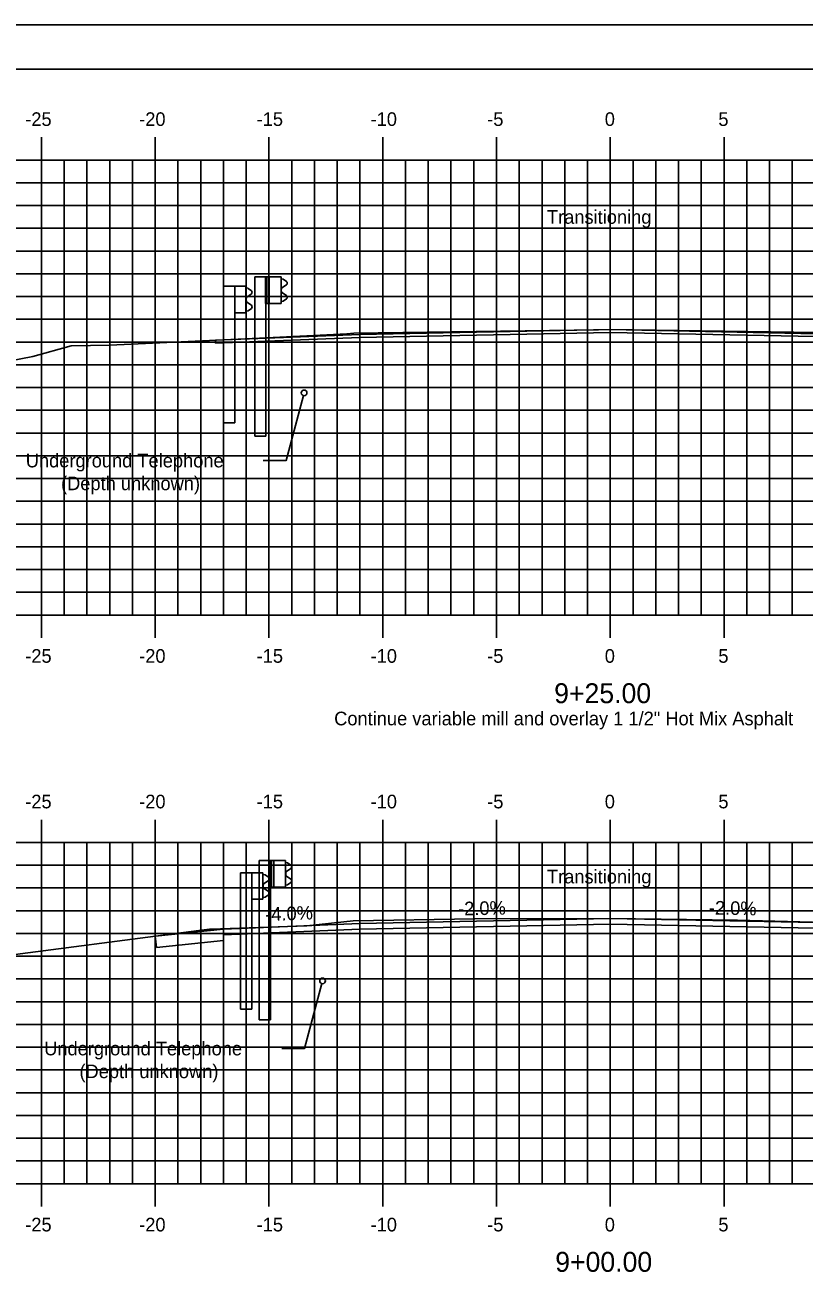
# Model space of a CAD drawing. Extents: x 2194502 to 2194968, y 863888 to 863998.
# Drawn here: x 2194672.8 to 2194707, y 863943.5 to 863998.4 of the extents above; entities that cross this region are included whole.
import ezdxf

# ---------------------------------------------------------------- set-up
doc = ezdxf.new("R2010")
doc.units = 0
for name, color, linetype in [('ANNOTATION', 7, 'Continuous'), ('BORDER', 7, 'Continuous'), ('D_Guardrail_Beam_Lt', 7, 'Continuous'), ('H_V ANNOTATION', 7, 'Continuous'), ('MAJOR', 7, 'Continuous'), ('MINOR', 7, 'Continuous'), ('PLOT BOUNDARY', 7, 'Continuous'), ('S_Guardrail_Beam', 7, 'Continuous'), ('S_Roadway_Centerline', 7, 'Continuous'), ('S_Utilities_Pole_Power', 7, 'Continuous'), ('TEMPLATE', 7, 'Continuous')]:
    doc.layers.add(name, color=color, linetype=linetype)

msp = doc.modelspace()

# ---------------------------------------------------------------- linework, layer by layer
at = {"layer": 'ANNOTATION'}
for points in [[(2194683.247, 863979.236), (2194684.247, 863979.236), (2194685.012, 863982.09)], [(2194684.057, 863953.387), (2194685.057, 863953.387), (2194685.822, 863956.241)]]:
    msp.add_lwpolyline(points, dxfattribs=at)
at = {"layer": 'BORDER'}
msp.add_lwpolyline([(2194623.499, 863891.446), (2194783.499, 863891.446), (2194783.499, 863996.446), (2194623.499, 863996.446)], close=True, dxfattribs=at)
at = {"layer": 'D_Guardrail_Beam_Lt'}
for p, q in [((2194682.871, 863987.31), (2194682.871, 863980.31)), ((2194683.342, 863987.31), (2194682.871, 863987.31)), ((2194684.029, 863987.31), (2194683.342, 863987.31)), ((2194683.342, 863987.31), (2194683.342, 863986.144)), ((2194683.404, 863987.31), (2194683.404, 863986.144)), ((2194683.509, 863987.31), (2194683.509, 863986.144)), ((2194684.029, 863986.144), (2194684.029, 863987.31)), ((2194684.029, 863987.227), (2194684.104, 863987.212)), ((2194684.263, 863986.962), (2194684.068, 863986.826)), ((2194684.119, 863987.206), (2194684.263, 863987.106)), ((2194684.034, 863986.762), (2194684.034, 863986.692)), ((2194684.068, 863986.627), (2194684.263, 863986.491)), ((2194683.342, 863986.144), (2194684.029, 863986.144)), ((2194683.363, 863980.31), (2194683.363, 863986.144)), ((2194684.104, 863986.241), (2194684.029, 863986.227)), ((2194684.263, 863986.348), (2194684.119, 863986.248)), ((2194683.363, 863980.31), (2194682.871, 863980.31)), ((2194683.07, 863961.652), (2194683.07, 863954.652)), ((2194683.541, 863961.652), (2194683.07, 863961.652)), ((2194684.228, 863961.652), (2194683.541, 863961.652)), ((2194683.541, 863961.652), (2194683.541, 863960.486)), ((2194683.603, 863961.652), (2194683.603, 863960.486)), ((2194683.708, 863961.652), (2194683.708, 863960.486)), ((2194684.228, 863960.486), (2194684.228, 863961.652)), ((2194684.228, 863961.569), (2194684.303, 863961.555)), ((2194684.462, 863961.305), (2194684.267, 863961.169)), ((2194684.318, 863961.548), (2194684.462, 863961.448)), ((2194684.233, 863961.104), (2194684.233, 863961.034)), ((2194684.267, 863960.97), (2194684.462, 863960.833)), ((2194684.462, 863960.69), (2194684.318, 863960.59)), ((2194683.541, 863960.486), (2194684.228, 863960.486)), ((2194683.562, 863954.652), (2194683.562, 863960.486)), ((2194684.303, 863960.584), (2194684.228, 863960.569)), ((2194683.562, 863954.652), (2194683.07, 863954.652))]:
    msp.add_line(p, q, dxfattribs=at)
for centre, major_axis, start_param, end_param in [((2194684.096, 863987.172), (0.0417, 0), 0.959931, 1.376053), ((2194684.213, 863987.034), (0.0877, 0), 5.323254, 7.243116), ((2194684.113, 863986.762), (-0.0789, 0), 5.323254, 6.283185), ((2194684.113, 863986.692), (-0.0789, 0), 6.283185, 7.243116), ((2194684.213, 863986.42), (0.0877, 0), 5.323254, 7.243116), ((2194684.096, 863986.282), (0.0417, 0), 4.907132, 5.323254), ((2194684.312, 863961.104), (-0.0789, 0), 5.323254, 6.283185), ((2194684.295, 863961.514), (0.0417, 0), 0.959931, 1.376053), ((2194684.412, 863961.376), (0.0877, 0), 5.323254, 7.243116), ((2194684.312, 863961.034), (-0.0789, 0), 6.283185, 7.243116), ((2194684.412, 863960.762), (0.0877, 0), 5.323254, 7.243116), ((2194684.295, 863960.624), (0.0417, 0), 4.907132, 5.323254)]:
    msp.add_ellipse(centre, major_axis=major_axis, ratio=0.995501, start_param=start_param, end_param=end_param, dxfattribs=at)
at = {"layer": 'MAJOR'}
for p, q in [((2194673.499, 863993.448), (2194673.499, 863992.446)), ((2194678.499, 863993.448), (2194678.499, 863992.446)), ((2194683.499, 863993.448), (2194683.499, 863992.446)), ((2194688.499, 863993.448), (2194688.499, 863992.446)), ((2194693.499, 863993.448), (2194693.499, 863992.446)), ((2194698.499, 863993.448), (2194698.499, 863992.446)), ((2194703.499, 863993.448), (2194703.499, 863992.446)), ((2194628.499, 863992.446), (2194768.499, 863992.446)), ((2194628.499, 863992.446), (2194768.499, 863992.446)), ((2194673.499, 863972.446), (2194673.499, 863992.446)), ((2194678.499, 863972.446), (2194678.499, 863992.446)), ((2194683.499, 863972.446), (2194683.499, 863992.446)), ((2194688.499, 863972.446), (2194688.499, 863992.446)), ((2194693.499, 863972.446), (2194693.499, 863992.446)), ((2194698.499, 863972.446), (2194698.499, 863992.446)), ((2194703.499, 863972.446), (2194703.499, 863992.446)), ((2194628.499, 863987.446), (2194768.499, 863987.446)), ((2194628.499, 863982.446), (2194768.499, 863982.446)), ((2194628.499, 863977.446), (2194768.499, 863977.446)), ((2194628.499, 863972.446), (2194768.499, 863972.446)), ((2194673.499, 863971.444), (2194673.499, 863972.446)), ((2194678.499, 863971.444), (2194678.499, 863972.446)), ((2194683.499, 863971.444), (2194683.499, 863972.446)), ((2194688.499, 863971.444), (2194688.499, 863972.446)), ((2194693.499, 863971.444), (2194693.499, 863972.446)), ((2194698.499, 863971.444), (2194698.499, 863972.446)), ((2194703.499, 863971.444), (2194703.499, 863972.446)), ((2194673.499, 863963.448), (2194673.499, 863962.446)), ((2194678.499, 863963.448), (2194678.499, 863962.446)), ((2194683.499, 863963.448), (2194683.499, 863962.446)), ((2194688.499, 863963.448), (2194688.499, 863962.446)), ((2194693.499, 863963.448), (2194693.499, 863962.446)), ((2194698.499, 863963.448), (2194698.499, 863962.446)), ((2194703.499, 863963.448), (2194703.499, 863962.446)), ((2194628.499, 863962.446), (2194768.499, 863962.446)), ((2194673.499, 863947.446), (2194673.499, 863962.446)), ((2194678.499, 863947.446), (2194678.499, 863962.446)), ((2194683.499, 863947.446), (2194683.499, 863962.446)), ((2194688.499, 863947.446), (2194688.499, 863962.446)), ((2194693.499, 863947.446), (2194693.499, 863962.446)), ((2194698.499, 863947.446), (2194698.499, 863962.446)), ((2194703.499, 863947.446), (2194703.499, 863962.446)), ((2194628.499, 863957.446), (2194768.499, 863957.446)), ((2194628.499, 863952.446), (2194768.499, 863952.446)), ((2194628.499, 863947.446), (2194768.499, 863947.446)), ((2194673.499, 863946.444), (2194673.499, 863947.446)), ((2194678.499, 863946.444), (2194678.499, 863947.446)), ((2194683.499, 863946.444), (2194683.499, 863947.446)), ((2194688.499, 863946.444), (2194688.499, 863947.446)), ((2194693.499, 863946.444), (2194693.499, 863947.446)), ((2194698.499, 863946.444), (2194698.499, 863947.446)), ((2194703.499, 863946.444), (2194703.499, 863947.446))]:
    msp.add_line(p, q, dxfattribs=at)
at = {"layer": 'MINOR'}
for p, q in [((2194674.499, 863972.446), (2194674.499, 863992.446)), ((2194675.499, 863972.446), (2194675.499, 863992.446)), ((2194676.499, 863972.446), (2194676.499, 863992.446)), ((2194677.499, 863972.446), (2194677.499, 863992.446)), ((2194679.499, 863972.446), (2194679.499, 863992.446)), ((2194680.499, 863972.446), (2194680.499, 863992.446)), ((2194681.499, 863972.446), (2194681.499, 863992.446)), ((2194682.499, 863972.446), (2194682.499, 863992.446)), ((2194684.499, 863972.446), (2194684.499, 863992.446)), ((2194685.499, 863972.446), (2194685.499, 863992.446)), ((2194686.499, 863972.446), (2194686.499, 863992.446)), ((2194687.499, 863972.446), (2194687.499, 863992.446)), ((2194689.499, 863972.446), (2194689.499, 863992.446)), ((2194690.499, 863972.446), (2194690.499, 863992.446)), ((2194691.499, 863972.446), (2194691.499, 863992.446)), ((2194692.499, 863972.446), (2194692.499, 863992.446)), ((2194694.499, 863972.446), (2194694.499, 863992.446)), ((2194695.499, 863972.446), (2194695.499, 863992.446)), ((2194696.499, 863972.446), (2194696.499, 863992.446)), ((2194697.499, 863972.446), (2194697.499, 863992.446)), ((2194699.499, 863972.446), (2194699.499, 863992.446)), ((2194700.499, 863972.446), (2194700.499, 863992.446)), ((2194701.499, 863972.446), (2194701.499, 863992.446)), ((2194702.499, 863972.446), (2194702.499, 863992.446)), ((2194704.499, 863972.446), (2194704.499, 863992.446)), ((2194705.499, 863972.446), (2194705.499, 863992.446)), ((2194706.499, 863972.446), (2194706.499, 863992.446)), ((2194628.499, 863991.446), (2194768.499, 863991.446)), ((2194628.499, 863990.446), (2194768.499, 863990.446)), ((2194628.499, 863989.446), (2194768.499, 863989.446)), ((2194628.499, 863988.446), (2194768.499, 863988.446)), ((2194628.499, 863986.446), (2194768.499, 863986.446)), ((2194628.499, 863985.446), (2194768.499, 863985.446)), ((2194628.499, 863984.446), (2194768.499, 863984.446)), ((2194628.499, 863983.446), (2194768.499, 863983.446)), ((2194628.499, 863981.446), (2194768.499, 863981.446)), ((2194628.499, 863980.446), (2194768.499, 863980.446)), ((2194628.499, 863979.446), (2194768.499, 863979.446)), ((2194628.499, 863978.446), (2194768.499, 863978.446)), ((2194628.499, 863976.446), (2194768.499, 863976.446)), ((2194628.499, 863975.446), (2194768.499, 863975.446)), ((2194628.499, 863974.446), (2194768.499, 863974.446)), ((2194628.499, 863973.446), (2194768.499, 863973.446)), ((2194674.499, 863947.446), (2194674.499, 863962.446)), ((2194675.499, 863947.446), (2194675.499, 863962.446)), ((2194676.499, 863947.446), (2194676.499, 863962.446)), ((2194677.499, 863947.446), (2194677.499, 863962.446)), ((2194679.499, 863947.446), (2194679.499, 863962.446)), ((2194680.499, 863947.446), (2194680.499, 863962.446)), ((2194681.499, 863947.446), (2194681.499, 863962.446)), ((2194682.499, 863947.446), (2194682.499, 863962.446)), ((2194684.499, 863947.446), (2194684.499, 863962.446)), ((2194685.499, 863947.446), (2194685.499, 863962.446)), ((2194686.499, 863947.446), (2194686.499, 863962.446)), ((2194687.499, 863947.446), (2194687.499, 863962.446)), ((2194689.499, 863947.446), (2194689.499, 863962.446)), ((2194690.499, 863947.446), (2194690.499, 863962.446)), ((2194691.499, 863947.446), (2194691.499, 863962.446)), ((2194692.499, 863947.446), (2194692.499, 863962.446)), ((2194694.499, 863947.446), (2194694.499, 863962.446)), ((2194695.499, 863947.446), (2194695.499, 863962.446)), ((2194696.499, 863947.446), (2194696.499, 863962.446)), ((2194697.499, 863947.446), (2194697.499, 863962.446)), ((2194699.499, 863947.446), (2194699.499, 863962.446)), ((2194700.499, 863947.446), (2194700.499, 863962.446)), ((2194701.499, 863947.446), (2194701.499, 863962.446)), ((2194702.499, 863947.446), (2194702.499, 863962.446)), ((2194704.499, 863947.446), (2194704.499, 863962.446)), ((2194705.499, 863947.446), (2194705.499, 863962.446)), ((2194706.499, 863947.446), (2194706.499, 863962.446)), ((2194628.499, 863961.446), (2194768.499, 863961.446)), ((2194628.499, 863960.446), (2194768.499, 863960.446)), ((2194628.499, 863959.446), (2194768.499, 863959.446)), ((2194628.499, 863958.446), (2194768.499, 863958.446)), ((2194628.499, 863956.446), (2194768.499, 863956.446)), ((2194628.499, 863955.446), (2194768.499, 863955.446)), ((2194628.499, 863954.446), (2194768.499, 863954.446)), ((2194628.499, 863953.446), (2194768.499, 863953.446)), ((2194628.499, 863951.446), (2194768.499, 863951.446)), ((2194628.499, 863950.446), (2194768.499, 863950.446)), ((2194628.499, 863949.446), (2194768.499, 863949.446)), ((2194628.499, 863948.446), (2194768.499, 863948.446))]:
    msp.add_line(p, q, dxfattribs=at)
at = {"layer": 'PLOT BOUNDARY'}
msp.add_lwpolyline([(2194615.406, 863888.387), (2194785.406, 863888.387), (2194785.406, 863998.387), (2194615.406, 863998.387)], close=True, dxfattribs=at)
at = {"layer": 'S_Guardrail_Beam'}
for p, q in [((2194681.5, 863986.898), (2194681.5, 863980.898)), ((2194681.992, 863986.898), (2194681.5, 863986.898)), ((2194682.482, 863986.898), (2194681.992, 863986.898)), ((2194681.992, 863986.898), (2194681.992, 863985.731)), ((2194682.482, 863985.731), (2194682.482, 863986.898)), ((2194682.482, 863986.825), (2194682.564, 863986.81)), ((2194682.724, 863986.56), (2194682.528, 863986.424)), ((2194682.58, 863986.803), (2194682.724, 863986.703)), ((2194682.495, 863986.36), (2194682.495, 863986.269)), ((2194682.528, 863986.204), (2194682.724, 863986.068)), ((2194682.724, 863985.925), (2194682.58, 863985.825)), ((2194681.992, 863980.898), (2194681.992, 863985.731)), ((2194681.992, 863985.731), (2194682.482, 863985.731)), ((2194682.564, 863985.818), (2194682.482, 863985.804)), ((2194681.992, 863980.898), (2194681.5, 863980.898)), ((2194682.253, 863961.116), (2194682.253, 863955.116)), ((2194682.745, 863961.116), (2194682.253, 863961.116)), ((2194683.234, 863961.116), (2194682.745, 863961.116)), ((2194682.745, 863961.116), (2194682.745, 863959.949)), ((2194683.234, 863959.949), (2194683.234, 863961.116)), ((2194683.234, 863961.043), (2194683.316, 863961.029)), ((2194683.477, 863960.779), (2194683.281, 863960.642)), ((2194683.333, 863961.022), (2194683.477, 863960.922)), ((2194683.248, 863960.578), (2194683.248, 863960.487)), ((2194683.281, 863960.423), (2194683.477, 863960.286)), ((2194683.477, 863960.143), (2194683.333, 863960.043)), ((2194682.745, 863955.116), (2194682.745, 863959.949)), ((2194682.745, 863959.949), (2194683.234, 863959.949)), ((2194683.316, 863960.037), (2194683.234, 863960.022)), ((2194682.745, 863955.116), (2194682.253, 863955.116))]:
    msp.add_line(p, q, dxfattribs=at)
for centre, major_axis, start_param, end_param in [((2194682.574, 863986.36), (-0.0789, 0), 5.323254, 6.283185), ((2194682.556, 863986.77), (0.0417, 0), 0.959931, 1.396263), ((2194682.673, 863986.632), (0.0877, 0), 5.323254, 7.243116), ((2194682.574, 863986.269), (-0.0789, 0), 6.283185, 7.243116), ((2194682.673, 863985.997), (0.0877, 0), 5.323254, 7.243116), ((2194682.556, 863985.859), (0.0417, 0), 4.886922, 5.323254), ((2194683.326, 863960.578), (-0.0789, 0), 5.323254, 6.283185), ((2194683.309, 863960.988), (0.0417, 0), 0.959931, 1.396263), ((2194683.426, 863960.85), (0.0877, 0), 5.323254, 7.243116), ((2194683.326, 863960.487), (-0.0789, 0), 6.283185, 7.243116), ((2194683.426, 863960.215), (0.0877, 0), 5.323254, 7.243116), ((2194683.309, 863960.077), (0.0417, 0), 4.886922, 5.323254)]:
    msp.add_ellipse(centre, major_axis=major_axis, ratio=0.995501, start_param=start_param, end_param=end_param, dxfattribs=at)
at = {"layer": 'S_Roadway_Centerline'}
for points in [[(2194666, 863982.427), (2194673.123, 863983.818), (2194674.81, 863984.278), (2194676.501, 863984.313), (2194683.393, 863984.628), (2194686.919, 863984.805), (2194687.224, 863984.838), (2194697.976, 863984.99), (2194698.502, 863984.991), (2194709.585, 863984.836), (2194710.081, 863984.824), (2194710.192, 863984.815), (2194712.436, 863984.681), (2194712.596, 863984.644), (2194714.834, 863984.124), (2194714.836, 863984.114), (2194716.134, 863983.876), (2194717.012, 863983.443), (2194731.656, 863978.954), (2194739.75, 863977.349), (2194747.963, 863976.289), (2194763.932, 863975.023), (2194764.031, 863975.023), (2194768.499, 863974.976)], [(2194670.976, 863957.344), (2194680.42, 863958.572), (2194680.878, 863958.638), (2194680.949, 863958.642), (2194685.157, 863958.786), (2194687.193, 863959.008), (2194692.54, 863959.083), (2194698.501, 863959.102), (2194704.085, 863959.024), (2194710.13, 863958.869), (2194711.477, 863958.767), (2194712.598, 863958.699), (2194714.403, 863958.284), (2194715.073, 863958.128), (2194715.095, 863958.006), (2194727.745, 863955.685), (2194729.344, 863955.492), (2194730.418, 863955.285), (2194733.533, 863954.397), (2194743.953, 863950.759), (2194747.523, 863950.45), (2194760.422, 863950.562), (2194768.499, 863950.601)]]:
    msp.add_lwpolyline(points, dxfattribs=at)
at = {"layer": 'S_Utilities_Pole_Power'}
for centre in [(2194685.044, 863982.211), (2194685.854, 863956.362)]:
    msp.add_circle(centre, 0.125, dxfattribs=at)
at = {"layer": 'TEMPLATE'}
for p, q in [((2194687.499, 863984.771), (2194681.15, 863984.526)), ((2194687.499, 863984.771), (2194698.499, 863984.991)), ((2194698.499, 863984.991), (2194687.499, 863984.771)), ((2194698.499, 863984.866), (2194687.499, 863984.646)), ((2194709.499, 863984.771), (2194698.499, 863984.991)), ((2194708.499, 863984.666), (2194698.499, 863984.866)), ((2194698.499, 863959.102), (2194687.499, 863958.882)), ((2194709.499, 863958.882), (2194698.499, 863959.102)), ((2194681.499, 863958.642), (2194678.499, 863958.322)), ((2194687.499, 863958.882), (2194681.499, 863958.642)), ((2194698.499, 863958.852), (2194687.499, 863958.632)), ((2194708.499, 863958.652), (2194698.499, 863958.852)), ((2194678.499, 863958.322), (2194678.552, 863957.828))]:
    msp.add_line(p, q, dxfattribs=at)
for points in [[(2194687.499, 863984.646), (2194681.15, 863984.401), (2194681.15, 863984.526)], [(2194687.499, 863958.632), (2194681.499, 863958.392), (2194681.499, 863958.642)], [(2194681.499, 863958.392), (2194681.499, 863958.142), (2194678.552, 863957.828)]]:
    msp.add_lwpolyline(points, dxfattribs=at)

# ---------------------------------------------------------------- texts
at = {"layer": 'ANNOTATION'}
for s, p in [('Transitioning', (2194695.716, 863989.646)), ('Underground Telephone', (2194672.808, 863978.936)), ('(Depth unknown)', (2194674.358, 863977.934)), ('Continue variable mill and overlay 1 1/2" Hot Mix Asphalt', (2194686.364, 863967.596)), ('Transitioning', (2194695.716, 863960.646)), ('Underground Telephone', (2194673.618, 863953.087)), ('(Depth unknown)', (2194675.168, 863952.085))]:
    msp.add_text(s, height=0.6, dxfattribs=at).set_placement(p)
for s, rotation, p in [('-4.0%', 2.2906, (2194683.344, 863958.983)), ('-2.0%', 1.1458, (2194691.817, 863959.235)), ('-2.0%', 358.8542, (2194702.828, 863959.282))]:
    msp.add_text(s, height=0.6, rotation=rotation, dxfattribs=at).set_placement(p)
at = {"layer": 'H_V ANNOTATION'}
for s, height, p in [('-25', 0.6, (2194672.785, 863993.946)), ('-20', 0.6, (2194677.793, 863993.946)), ('-15', 0.6, (2194682.956, 863993.946)), ('-10', 0.6, (2194687.964, 863993.946)), ('-5', 0.6, (2194693.09, 863993.946)), ('0', 0.6, (2194698.258, 863993.946)), ('5', 0.6, (2194703.25, 863993.946)), ('-25', 0.6, (2194672.785, 863970.346)), ('-20', 0.6, (2194677.793, 863970.346)), ('-15', 0.6, (2194682.956, 863970.346)), ('-10', 0.6, (2194687.964, 863970.346)), ('-5', 0.6, (2194693.09, 863970.346)), ('0', 0.6, (2194698.258, 863970.346)), ('5', 0.6, (2194703.25, 863970.346)), ('9+25.00', 0.875, (2194696.034, 863968.571)), ('-25', 0.6, (2194672.785, 863963.946)), ('-20', 0.6, (2194677.793, 863963.946)), ('-15', 0.6, (2194682.956, 863963.946)), ('-10', 0.6, (2194687.964, 863963.946)), ('-5', 0.6, (2194693.09, 863963.946)), ('0', 0.6, (2194698.258, 863963.946)), ('5', 0.6, (2194703.25, 863963.946)), ('-25', 0.6, (2194672.785, 863945.346)), ('-20', 0.6, (2194677.793, 863945.346)), ('-15', 0.6, (2194682.956, 863945.346)), ('-10', 0.6, (2194687.964, 863945.346)), ('-5', 0.6, (2194693.09, 863945.346)), ('0', 0.6, (2194698.258, 863945.346)), ('5', 0.6, (2194703.25, 863945.346)), ('9+00.00', 0.875, (2194696.08, 863943.571))]:
    msp.add_text(s, height=height, dxfattribs=at).set_placement(p)

doc.saveas('drawing.dxf')
